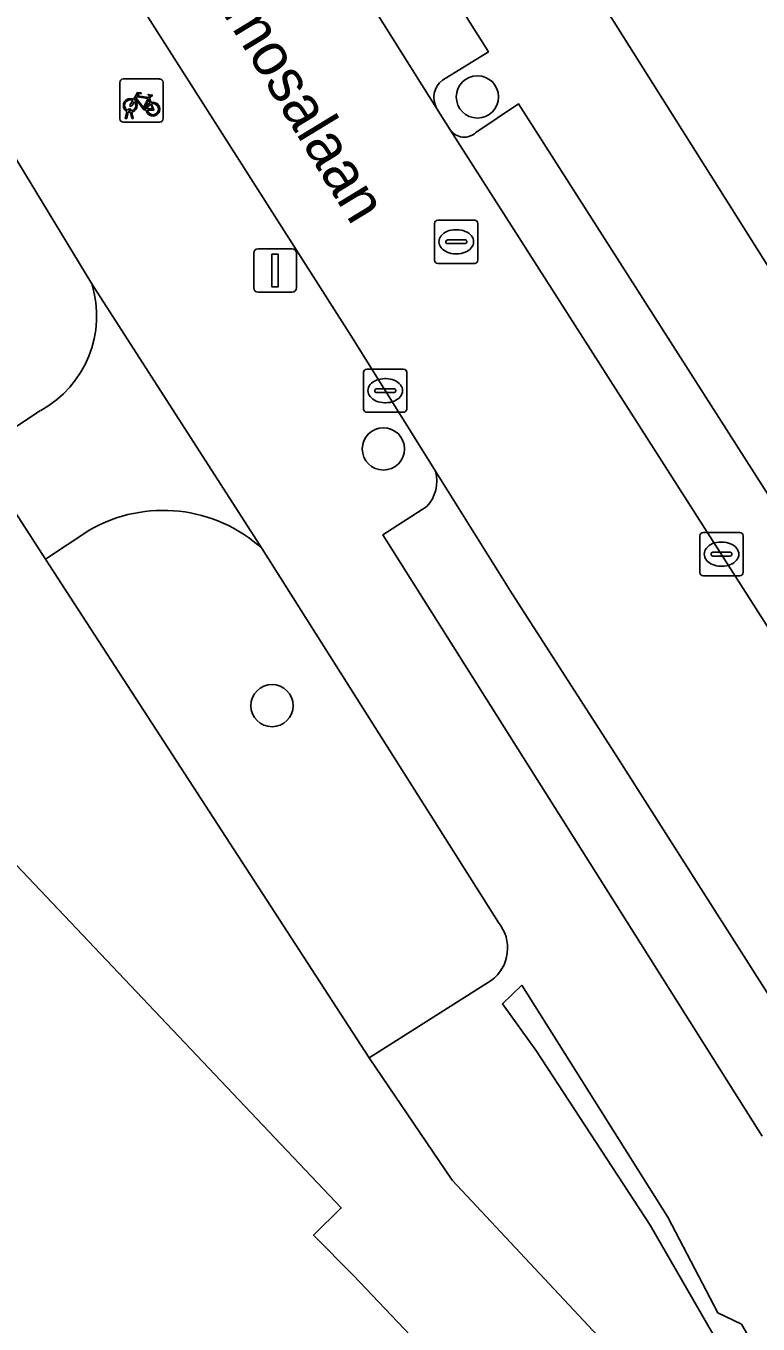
# Model space of a CAD drawing. Extents: x 162344 to 162869, y 381217 to 381818.
# Drawn here: x 162595.97 to 162612.92, y 381421.83 to 381451.9 of the extents above; entities that cross this region are included whole.
import ezdxf

# ---------------------------------------------------------------- set-up
doc = ezdxf.new("R2010")
doc.units = 0
for name, color, linetype in [('IMGEO_Boom', 7, 'Continuous'), ('IMGEO_Erf', 7, 'Continuous'), ('IMGEO_Fietsenrek', 7, 'Continuous'), ('IMGEO_Groenvoorziening', 7, 'Continuous'), ('IMGEO_Haag', 7, 'Continuous'), ('IMGEO_Kolk', 7, 'Continuous'), ('IMGEO_Lichtmast', 7, 'Continuous'), ('IMGEO_Openbare_ruimte_label', 7, 'Continuous'), ('IMGEO_Pand', 7, 'Continuous'), ('IMGEO_Parkeervlak_open', 7, 'Continuous'), ('IMGEO_Rijbaan_lokaal_gesloten', 7, 'Continuous'), ('IMGEO_Rioolput', 7, 'Continuous'), ('IMGEO_Voetpad_open', 7, 'Continuous')]:
    doc.layers.add(name, color=color, linetype=linetype)

msp = doc.modelspace()

# ---------------------------------------------------------------- linework, layer by layer
at = {"layer": 'IMGEO_Boom'}
for centre in [(162606.426, 381450.254), (162604.249, 381442.1), (162601.67, 381436.154)]:
    msp.add_circle(centre, 0.489, dxfattribs=at)
at = {"layer": 'IMGEO_Erf'}
for points in [[(162622.037, 381407.841), (162605.841, 381425.165), (162603.922, 381427.994), (162596.425, 381439.548), (162594.828, 381442.012), (162591.287, 381447.468), (162588.885, 381451.187), (162575.654, 381472.131), (162574.139, 381474.467), (162572.367, 381477.268), (162564.943, 381472.596), (162566.7, 381469.803), (162563.061, 381467.513), (162561.304, 381470.306), (162550.724, 381463.648), (162554.763, 381457.01), (162544.461, 381450.664), (162552.634, 381437.722), (162563.756, 381419.355)], [(162572.717, 381468.186), (162577.548, 381460.536), (162580.455, 381462.371), (162583.242, 381457.957), (162580.287, 381456.091), (162585.166, 381448.364), (162585.665, 381448.66), (162587.593, 381445.608), (162587.102, 381445.298), (162590.813, 381439.422), (162590.01, 381438.915), (162592.432, 381435.079), (162592.952, 381435.408), (162603.272, 381424.519), (162602.633, 381423.885), (162603.56, 381422.951), (162608.827, 381417.399)]]:
    msp.add_lwpolyline(points, dxfattribs=at)
msp.add_lwpolyline([(162600.252, 381466.808), (162628.211, 381422.438), (162631.131, 381424.361), (162627.522, 381430.077), (162624.077, 381435.533), (162620.587, 381441.059), (162617.109, 381446.568), (162613.625, 381452.085), (162610.21, 381457.494), (162606.701, 381463.05), (162603.166, 381468.649)], close=True, dxfattribs=at)
at = {"layer": 'IMGEO_Fietsenrek'}
for p, q in [((162598.147, 381449.744), (162598.147, 381450.585)), ((162598.147, 381450.585), (162598.147, 381449.744)), ((162598.222, 381450.669), (162599.063, 381450.669)), ((162599.063, 381450.669), (162598.222, 381450.669)), ((162599.147, 381450.594), (162599.147, 381449.753)), ((162599.147, 381449.753), (162599.147, 381450.594)), ((162598.385, 381449.925), (162598.384, 381449.929)), ((162598.416, 381449.936), (162598.417, 381449.929)), ((162598.834, 381450.218), (162598.87, 381450.123)), ((162599.072, 381449.669), (162598.231, 381449.669)), ((162598.231, 381449.669), (162599.072, 381449.669)), ((162598.274, 381449.753), (162598.313, 381449.913)), ((162598.308, 381449.753), (162598.274, 381449.753)), ((162598.343, 381449.901), (162598.308, 381449.753)), ((162598.426, 381449.753), (162598.392, 381449.895)), ((162598.424, 381449.899), (162598.459, 381449.753)), ((162598.459, 381449.753), (162598.426, 381449.753))]:
    msp.add_line(p, q, dxfattribs=at)
for points in [[(162598.46, 381450.195), (162598.555, 381450.359), (162598.641, 381450.345), (162598.643, 381450.336), (162598.587, 381450.325), (162598.56, 381450.28), (162598.816, 381450.239)], [(162598.803, 381450.214), (162598.546, 381450.255), (162598.529, 381450.226), (162598.696, 381450.006), (162598.803, 381450.214)], [(162598.816, 381450.239), (162598.841, 381450.288), (162598.835, 381450.292), (162598.812, 381450.296), (162598.8, 381450.303), (162598.799, 381450.306), (162598.801, 381450.311), (162598.896, 381450.296), (162598.898, 381450.286), (162598.888, 381450.273), (162598.876, 381450.267), (162598.862, 381450.273), (162598.834, 381450.218)], [(162598.481, 381450.143), (162598.429, 381450.053), (162598.389, 381450.028), (162598.39, 381450.075), (162598.445, 381450.169)], [(162598.756, 381449.951), (162598.706, 381449.951), (162598.515, 381450.202), (162598.496, 381450.17)], [(162598.851, 381450.116), (162598.821, 381450.193), (162598.712, 381449.975), (162598.755, 381449.975)], [(162598.785, 381449.975), (162598.905, 381449.974), (162598.861, 381450.088)], [(162598.881, 381450.095), (162598.936, 381449.95), (162598.786, 381449.95)]]:
    msp.add_lwpolyline(points, dxfattribs=at)
for centre, radius, start, end in [((162598.225, 381450.591), 0.0779, 92.4484, 184.2845), ((162598.225, 381450.591), 0.0779, 92.4484, 184.2845), ((162599.069, 381450.591), 0.0779, 2.4484, 94.2845), ((162599.069, 381450.591), 0.0779, 2.4484, 94.2845), ((162598.387, 381450.054), 0.159, 62.6766, 242.1369), ((162598.387, 381450.054), 0.129, 63.3192, 238.903), ((162598.367, 381449.925), 0.0499, 12.8025, 158.6934), ((162598.367, 381449.925), 0.0174, 12.8025, 163.4502), ((162598.387, 381450.054), 0.129, 253.415, 269.0204), ((162598.387, 381450.054), 0.129, 283.6043, 43.4302), ((162598.387, 381450.054), 0.159, 283.5766, 46.6042), ((162598.914, 381449.97), 0.159, 113.3408, 178.3217), ((162598.914, 381449.97), 0.159, 187.0065, 105.7708), ((162598.914, 381449.97), 0.129, 113.923, 177.9556), ((162598.914, 381449.97), 0.129, 188.6715, 104.5883), ((162598.225, 381449.747), 0.0779, 182.4484, 274.2845), ((162598.225, 381449.747), 0.0779, 182.4484, 274.2845), ((162598.387, 381450.054), 0.159, 253.9967, 271.7867), ((162599.069, 381449.747), 0.0779, 272.4484, 4.2845), ((162599.069, 381449.747), 0.0779, 272.4484, 4.2845)]:
    msp.add_arc(centre, radius, start, end, dxfattribs=at)
at = {"layer": 'IMGEO_Groenvoorziening'}
for points in [[(162578.867, 381474.091), (162577.756, 381473.413), (162575.654, 381472.131), (162588.885, 381451.187), (162591.287, 381447.468), (162594.828, 381442.012), (162596.314, 381442.992)], [(162597.498, 381445.923), (162595.651, 381448.964), (162592.214, 381454.371), (162579.893, 381473.779)], [(162597.449, 381440.223), (162596.425, 381439.548), (162603.922, 381427.994), (162606.747, 381429.79)], [(162606.912, 381431.128), (162601.446, 381439.786)]]:
    msp.add_lwpolyline(points, dxfattribs=at)
msp.add_lwpolyline([(162607.456, 381429.681), (162607.003, 381429.243), (162607.797, 381428.153), (162610.422, 381424.115), (162612.605, 381420.345), (162612.827, 381420.341), (162612.803, 381421.373), (162612.539, 381421.823), (162611.993, 381422.086), (162610.836, 381424.301)], close=True, dxfattribs=at)
for centre, radius, start, end in [((162595.114, 381445.182), 2.497, 298.7345, 17.2722), ((162599.148, 381437.265), 3.411, 47.6476, 119.8734), ((162606.198, 381430.537), 0.927, 306.3071, 39.6326)]:
    msp.add_arc(centre, radius, start, end, dxfattribs=at)
at = {"layer": 'IMGEO_Haag'}
msp.add_lwpolyline([(162607.456, 381429.681), (162607.003, 381429.243), (162607.797, 381428.153), (162610.422, 381424.115), (162612.605, 381420.345), (162612.827, 381420.341), (162612.803, 381421.373), (162612.539, 381421.823), (162611.993, 381422.086), (162610.836, 381424.301)], close=True, dxfattribs=at)
at = {"layer": 'IMGEO_Kolk'}
for p, q in [((162603.866, 381443.949), (162604.718, 381443.949)), ((162603.791, 381443.023), (162603.791, 381443.875)), ((162604.279, 381443.729), (162604.304, 381443.729)), ((162604.792, 381443.875), (162604.792, 381443.023)), ((162604.05, 381443.443), (162604.05, 381443.455)), ((162604.488, 381443.406), (162604.09, 381443.406)), ((162604.093, 381443.492), (162604.491, 381443.492)), ((162604.534, 381443.455), (162604.534, 381443.443)), ((162604.302, 381443.169), (162604.277, 381443.169)), ((162604.718, 381442.949), (162603.866, 381442.949)), ((162611.576, 381439.236), (162611.576, 381440.088)), ((162611.651, 381440.162), (162612.503, 381440.162)), ((162612.577, 381440.088), (162612.577, 381439.236)), ((162611.878, 381439.705), (162612.276, 381439.705)), ((162612.064, 381439.942), (162612.089, 381439.942)), ((162611.835, 381439.656), (162611.835, 381439.668)), ((162612.273, 381439.619), (162611.875, 381439.619)), ((162612.319, 381439.668), (162612.319, 381439.656)), ((162612.503, 381439.162), (162611.651, 381439.162)), ((162612.087, 381439.382), (162612.062, 381439.382))]:
    msp.add_line(p, q, dxfattribs=at)
for points in [[(162603.866, 381443.949), (162604.718, 381443.949)], [(162603.791, 381443.023), (162603.791, 381443.875)], [(162604.792, 381443.875), (162604.792, 381443.023)], [(162604.718, 381442.949), (162603.866, 381442.949)], [(162611.576, 381439.236), (162611.576, 381440.088)], [(162611.651, 381440.162), (162612.503, 381440.162)], [(162612.577, 381440.088), (162612.577, 381439.236)], [(162612.503, 381439.162), (162611.651, 381439.162)]]:
    msp.add_lwpolyline(points, dxfattribs=at)
for centre, radius, start, end in [((162603.868, 381443.873), 0.0765, 91.552, 178.448), ((162603.868, 381443.873), 0.0765, 91.552, 178.448), ((162604.716, 381443.873), 0.0765, 1.552, 88.448), ((162604.716, 381443.873), 0.0765, 1.552, 88.448), ((162604.09, 381443.452), 0.0403, 85.8775, 175.7526), ((162604.087, 381443.442), 0.0366, 178.938, 274.7102), ((162604.491, 381443.449), 0.043, 264.8664, 352.4533), ((162604.495, 381443.454), 0.0386, 1.7309, 96.639), ((162603.868, 381443.025), 0.0765, 181.552, 268.448), ((162603.868, 381443.025), 0.0765, 181.552, 268.448), ((162604.716, 381443.025), 0.0765, 271.552, 358.448), ((162604.716, 381443.025), 0.0765, 271.552, 358.448), ((162611.653, 381440.086), 0.0765, 91.552, 178.448), ((162611.653, 381440.086), 0.0765, 91.552, 178.448), ((162612.501, 381440.086), 0.0765, 1.552, 88.448), ((162612.501, 381440.086), 0.0765, 1.552, 88.448), ((162611.875, 381439.665), 0.0403, 85.8775, 175.7526), ((162612.28, 381439.667), 0.0386, 1.7309, 96.639), ((162611.872, 381439.655), 0.0366, 178.938, 274.7102), ((162612.276, 381439.662), 0.043, 264.8664, 352.4533), ((162611.653, 381439.238), 0.0765, 181.552, 268.448), ((162611.653, 381439.238), 0.0765, 181.552, 268.448), ((162612.501, 381439.238), 0.0765, 271.552, 358.448), ((162612.501, 381439.238), 0.0765, 271.552, 358.448)]:
    msp.add_arc(centre, radius, start, end, dxfattribs=at)
for centre, major_axis, ratio, start_param, end_param in [((162604.278, 381443.449), (-0.387, 0.002), 0.722429, 4.712389, 7.853982), ((162604.303, 381443.449), (-0.39, 0.002), 0.717154, 1.570796, 4.712389), ((162612.063, 381439.662), (-0.387, 0.002), 0.722429, 4.712389, 7.853982), ((162612.088, 381439.662), (-0.39, 0.002), 0.717154, 1.570796, 4.712389)]:
    msp.add_ellipse(centre, major_axis=major_axis, ratio=ratio, start_param=start_param, end_param=end_param, dxfattribs=at)
at = {"layer": 'IMGEO_Lichtmast'}
for p, q in [((162601.246, 381445.833), (162601.246, 381446.633)), ((162601.246, 381446.633), (162601.246, 381445.833)), ((162601.346, 381446.733), (162602.136, 381446.733)), ((162602.136, 381446.733), (162601.346, 381446.733)), ((162602.236, 381446.633), (162602.236, 381445.833)), ((162602.236, 381445.833), (162602.236, 381446.633)), ((162602.136, 381445.733), (162601.346, 381445.733)), ((162601.346, 381445.733), (162602.136, 381445.733))]:
    msp.add_line(p, q, dxfattribs=at)
msp.add_lwpolyline([(162601.666, 381446.608), (162601.816, 381446.608), (162601.816, 381445.858), (162601.666, 381445.858), (162601.666, 381446.608)], dxfattribs=at)
for centre, start, end in [((162601.346, 381446.633), 90, 180), ((162601.346, 381446.633), 90, 180), ((162602.136, 381446.633), 0, 90), ((162602.136, 381446.633), 360, 90), ((162601.346, 381445.833), 180, 270), ((162601.346, 381445.833), 180, 270), ((162602.136, 381445.833), 270, 0), ((162602.136, 381445.833), 270, 0)]:
    msp.add_arc(centre, 0.1, start, end, dxfattribs=at)
at = {"layer": 'IMGEO_Pand'}
msp.add_lwpolyline([(162608.827, 381417.399), (162603.56, 381422.951), (162602.633, 381423.885), (162603.272, 381424.519), (162592.952, 381435.408), (162592.432, 381435.079), (162590.01, 381438.915), (162575.915, 381430.015), (162577.832, 381426.973), (162573.52, 381424.25), (162571.61, 381427.275), (162563.715, 381422.29), (162565.124, 381420.252)], dxfattribs=at)
at = {"layer": 'IMGEO_Parkeervlak_open'}
for points in [[(162605.619, 381450.643), (162606.681, 381451.298), (162597.847, 381465.289), (162596.709, 381464.607)], [(162596.087, 381464.752), (162601.154, 381456.882), (162605.481, 381449.991)], [(162615.299, 381435.415), (162616.348, 381436.032), (162607.375, 381450.097), (162606.389, 381449.43)], [(162605.798, 381449.492), (162615.118, 381434.889), (162615.07, 381435.013)], [(162621.654, 381417.672), (162619.85, 381419.909), (162618.43, 381421.705), (162616.235, 381424.738), (162614.534, 381427.306), (162609.601, 381435.057), (162607.233, 381438.741), (162605.459, 381441.582)], [(162605.258, 381440.763), (162604.234, 381440.108), (162613.017, 381426.18)]]:
    msp.add_lwpolyline(points, dxfattribs=at)
for centre, radius, start, end in [((162605.921, 381450.239), 0.504, 126.7084, 209.3903), ((162606.12, 381449.711), 0.389, 214.2601, 313.7623), ((162604.592, 381441.361), 0.894, 318.0845, 14.3373)]:
    msp.add_arc(centre, radius, start, end, dxfattribs=at)
at = {"layer": 'IMGEO_Rijbaan_lokaal_gesloten'}
msp.add_lwpolyline([(162624.194, 381421.482), (162622.707, 381423.487), (162619.556, 381427.86), (162615.628, 381434.046), (162615.487, 381434.272), (162615.118, 381434.889), (162605.798, 381449.492), (162605.481, 381449.991), (162601.154, 381456.882), (162596.087, 381464.752), (162596.011, 381464.87), (162593.509, 381468.912), (162589.756, 381466.45), (162596.967, 381454.988), (162603.511, 381444.701), (162605.459, 381441.582), (162607.233, 381438.741), (162609.601, 381435.057), (162614.534, 381427.306), (162616.235, 381424.738), (162618.43, 381421.705)], dxfattribs=at)
at = {"layer": 'IMGEO_Rioolput'}
for p, q in [((162605.435, 381446.472), (162605.435, 381447.324)), ((162605.51, 381447.398), (162606.362, 381447.398)), ((162606.436, 381447.324), (162606.436, 381446.472)), ((162605.737, 381446.941), (162606.135, 381446.941)), ((162605.923, 381447.178), (162605.948, 381447.178)), ((162605.694, 381446.892), (162605.694, 381446.904)), ((162606.132, 381446.855), (162605.734, 381446.855)), ((162605.946, 381446.618), (162605.921, 381446.618)), ((162606.178, 381446.904), (162606.178, 381446.892)), ((162606.362, 381446.398), (162605.51, 381446.398))]:
    msp.add_line(p, q, dxfattribs=at)
for points in [[(162605.435, 381446.472), (162605.435, 381447.324)], [(162605.51, 381447.398), (162606.362, 381447.398)], [(162606.436, 381447.324), (162606.436, 381446.472)], [(162606.362, 381446.398), (162605.51, 381446.398)]]:
    msp.add_lwpolyline(points, dxfattribs=at)
for centre, radius, start, end in [((162605.512, 381447.322), 0.0765, 91.552, 178.448), ((162605.512, 381447.322), 0.0765, 91.552, 178.448), ((162606.36, 381447.322), 0.0765, 1.552, 88.448), ((162606.36, 381447.322), 0.0765, 1.552, 88.448), ((162605.734, 381446.901), 0.0403, 85.8775, 175.7526), ((162606.139, 381446.903), 0.0386, 1.7309, 96.639), ((162605.731, 381446.891), 0.0366, 178.938, 274.7102), ((162606.135, 381446.898), 0.043, 264.8664, 352.4533), ((162605.512, 381446.474), 0.0765, 181.552, 268.448), ((162605.512, 381446.474), 0.0765, 181.552, 268.448), ((162606.36, 381446.474), 0.0765, 271.552, 358.448), ((162606.36, 381446.474), 0.0765, 271.552, 358.448)]:
    msp.add_arc(centre, radius, start, end, dxfattribs=at)
for centre, major_axis, ratio, start_param, end_param in [((162605.922, 381446.898), (-0.387, 0.002), 0.722429, 4.712389, 7.853982), ((162605.947, 381446.898), (-0.39, 0.002), 0.717154, 1.570796, 4.712389)]:
    msp.add_ellipse(centre, major_axis=major_axis, ratio=ratio, start_param=start_param, end_param=end_param, dxfattribs=at)
at = {"layer": 'IMGEO_Voetpad_open'}
for points in [[(162605.459, 381441.582), (162603.511, 381444.701), (162596.967, 381454.988), (162589.756, 381466.45), (162586.829, 381471.084), (162579.561, 381482.257)], [(162634.944, 381419.82), (162633.611, 381419.13), (162631.192, 381421.776), (162631.213, 381422.825), (162631.866, 381423.318), (162631.131, 381424.361), (162628.211, 381422.438), (162600.252, 381466.808), (162603.166, 381468.649), (162608.933, 381472.289), (162607.642, 381473.555), (162606.858, 381474.324), (162602.378, 381479.081), (162599.95, 381481.55)], [(162579.893, 381473.779), (162592.214, 381454.371), (162595.651, 381448.964), (162597.498, 381445.923), (162601.446, 381439.786), (162606.912, 381431.128)], [(162596.709, 381464.607), (162597.847, 381465.289), (162606.681, 381451.298), (162605.619, 381450.643)], [(162605.481, 381449.991), (162605.798, 381449.492)], [(162606.389, 381449.43), (162607.375, 381450.097), (162616.348, 381436.032), (162615.299, 381435.415)], [(162601.446, 381439.786), (162597.498, 381445.923)], [(162596.314, 381442.992), (162594.828, 381442.012), (162596.425, 381439.548), (162597.449, 381440.223)], [(162613.017, 381426.18), (162604.234, 381440.108), (162605.258, 381440.763)], [(162606.747, 381429.79), (162603.922, 381427.994), (162605.841, 381425.165), (162622.037, 381407.841)]]:
    msp.add_lwpolyline(points, dxfattribs=at)
msp.add_lwpolyline([(162607.456, 381429.681), (162610.836, 381424.301), (162611.993, 381422.086), (162612.539, 381421.823), (162612.803, 381421.373), (162612.827, 381420.341), (162612.605, 381420.345), (162610.422, 381424.115), (162607.797, 381428.153), (162607.003, 381429.243)], close=True, dxfattribs=at)
for centre, radius, start, end in [((162605.921, 381450.239), 0.504, 126.7084, 209.3903), ((162606.12, 381449.711), 0.389, 214.2601, 313.7623), ((162595.114, 381445.182), 2.497, 298.7345, 17.2722), ((162604.592, 381441.361), 0.894, 318.0845, 14.3373), ((162599.148, 381437.265), 3.411, 47.6476, 119.8734), ((162606.198, 381430.537), 0.927, 306.3071, 39.6326)]:
    msp.add_arc(centre, radius, start, end, dxfattribs=at)

# ---------------------------------------------------------------- texts
at = {"layer": 'IMGEO_Openbare_ruimte_label'}
msp.add_text('Mimosalaan', height=1, rotation=301.3372, dxfattribs=at).set_placement((162599.784, 381453.407))

doc.saveas('drawing.dxf')
